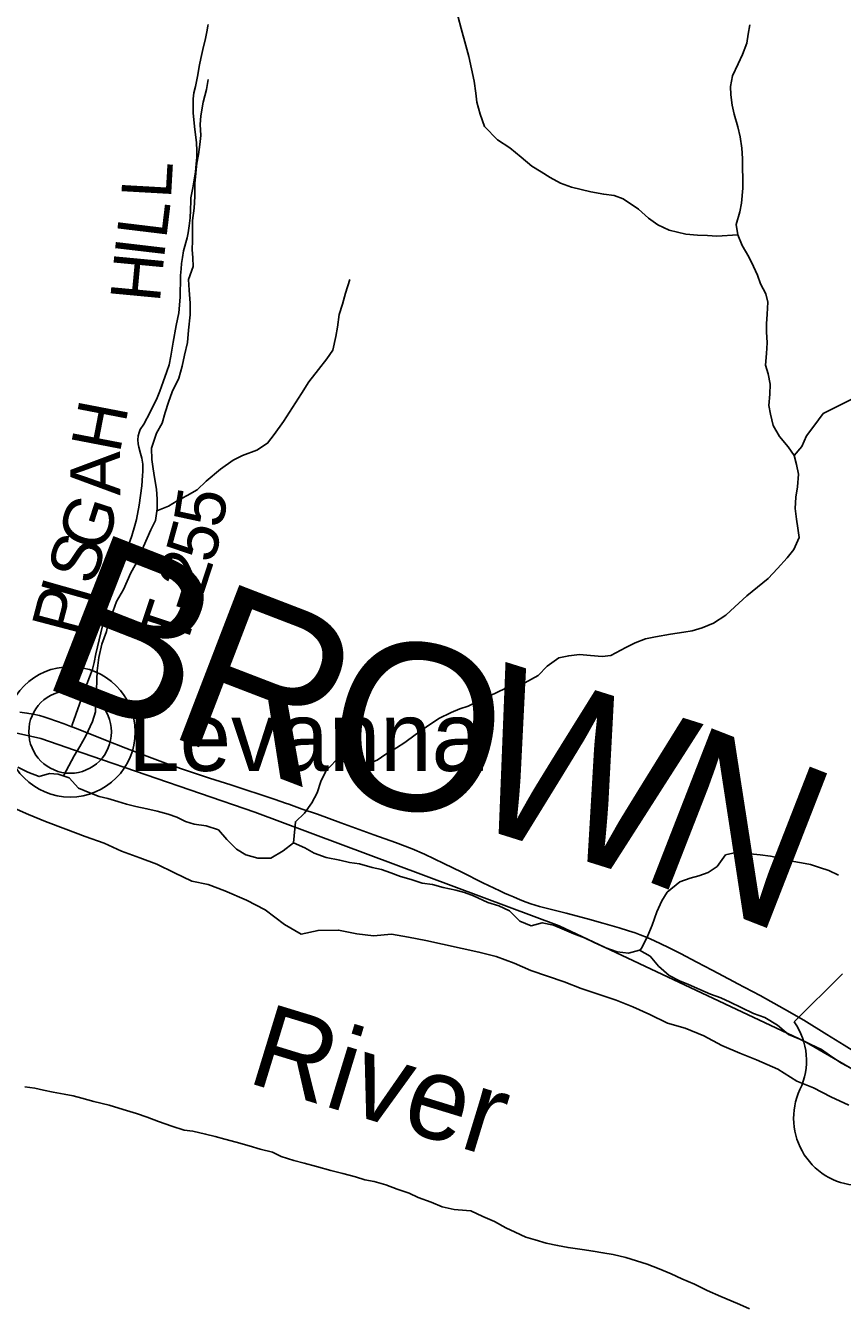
# Model space of a CAD drawing. Extents: x 0 to 34, y 0 to 22.
# Drawn here: x 3.024 to 3.956, y 18.308 to 19.77 of the extents above; entities that cross this region are included whole.
import ezdxf

# ---------------------------------------------------------------- set-up
doc = ezdxf.new("R2010")
doc.units = 0
for name, color, linetype in [('Default', 7, 'Continuous'), ('GM_X_County_Text', 7, 'Continuous'), ('GM_X_Major_River', 7, 'Continuous'), ('GM_X_Major_River_Text', 7, 'Continuous'), ('GM_X_Minor_River', 7, 'Continuous'), ('GM_X_Rail_Line', 7, 'Continuous'), ('GM_X_Township_Road', 7, 'Continuous'), ('GM_X_Township_Road_Text', 7, 'Continuous'), ('GM_X_Unincorporated', 7, 'Continuous'), ('GM_X_Unincorporated_Location', 7, 'Continuous'), ('GM_X_Unincorporated_Text', 7, 'Continuous'), ('GM_X_US_Route', 7, 'Continuous'), ('GM_X_US_Shield', 7, 'Continuous'), ('SH_Cut_Line', 7, 'Continuous')]:
    doc.layers.add(name, color=color, linetype=linetype)

msp = doc.modelspace()

# ---------------------------------------------------------------- linework, layer by layer
at = {"layer": 'Default'}
msp.add_lwpolyline([(3.0072, 18.8782), (3.0269, 18.8695), (3.0466, 18.8615), (3.0697, 18.8528), (3.0917, 18.8444), (3.1133, 18.8368), (3.1334, 18.8277), (3.1542, 18.8201), (3.1736, 18.8129), (3.1936, 18.8031), (3.2134, 18.7936), (3.2323, 18.7898), (3.2512, 18.7826), (3.2759, 18.7719), (3.2975, 18.7609), (3.3195, 18.7439), (3.3384, 18.7332), (3.3577, 18.7374), (3.3812, 18.7378), (3.4021, 18.7336), (3.421, 18.731), (3.4415, 18.7332), (3.4608, 18.7298), (3.4809, 18.7257), (3.5413, 18.7127), (3.561, 18.7074), (3.5815, 18.6998), (3.6006, 18.6915), (3.6386, 18.6786), (3.658, 18.671), (3.6777, 18.6645), (3.6982, 18.6577), (3.7171, 18.6501), (3.7365, 18.6413), (3.7569, 18.6315), (3.777, 18.6258), (3.7983, 18.617), (3.8187, 18.606), (3.8392, 18.5973), (3.8582, 18.5897), (3.8828, 18.5791), (3.9044, 18.5654), (3.9234, 18.5578), (3.9431, 18.5476), (3.9639, 18.5381)], dxfattribs=at)
at = {"layer": 'GM_X_Major_River'}
for points in [[(3.5353, 18.7768), (3.5251, 18.7807), (3.515, 18.7832), (3.5007, 18.7864), (3.4882, 18.7896), (3.4765, 18.7913), (3.4641, 18.7953), (3.4517, 18.7989), (3.4408, 18.8029), (3.4303, 18.8068), (3.4194, 18.8093), (3.4051, 18.8133), (3.3937, 18.815), (3.3824, 18.8174), (3.367, 18.8207), (3.3531, 18.8254), (3.3426, 18.8317), (3.3295, 18.8372), (3.318, 18.8282), (3.3039, 18.8197), (3.2891, 18.8199), (3.2752, 18.8236), (3.2647, 18.8302), (3.2535, 18.841), (3.2439, 18.8521), (3.23, 18.8565), (3.2164, 18.8586), (3.2062, 18.8618), (3.1965, 18.8665), (3.1867, 18.87), (3.1739, 18.8733), (3.1622, 18.8761), (3.1498, 18.8786), (3.1389, 18.8814), (3.1291, 18.8846), (3.1178, 18.8878), (3.1076, 18.8902), (3.0971, 18.8945), (3.0843, 18.8996), (3.0736, 18.9116), (3.0608, 18.9155), (3.051, 18.9165), (3.0392, 18.9128), (3.0264, 18.918), (3.0148, 18.9238)], [(3.9678, 18.5792), (3.9554, 18.5858), (3.9456, 18.5924), (3.9325, 18.6013), (3.9204, 18.6072), (3.908, 18.6134), (3.8948, 18.6185), (3.8824, 18.6293), (3.8678, 18.6379), (3.8549, 18.6426), (3.841, 18.6492), (3.8282, 18.6555), (3.8177, 18.6605), (3.806, 18.6645), (3.7935, 18.67), (3.7807, 18.6755), (3.7705, 18.6798), (3.7585, 18.686), (3.7465, 18.6964), (3.7368, 18.7079), (3.7247, 18.7149), (3.7122, 18.7113), (3.6993, 18.713), (3.6865, 18.7173), (3.6729, 18.7236), (3.662, 18.7287), (3.6499, 18.7334), (3.6364, 18.7393), (3.6266, 18.7432), (3.6137, 18.746), (3.6012, 18.7424), (3.5883, 18.7479), (3.5764, 18.7598), (3.5643, 18.7653), (3.5515, 18.7693), (3.5353, 18.7768)], [(3.0229, 18.5589), (3.0342, 18.5572), (3.044, 18.5552), (3.0553, 18.5527), (3.0677, 18.5506), (3.0779, 18.5486), (3.0881, 18.5458), (3.1016, 18.5422), (3.1193, 18.5381)], [(3.1193, 18.5381), (3.1351, 18.5329), (3.1505, 18.5285), (3.1626, 18.5242), (3.1754, 18.5194), (3.1908, 18.5139), (3.2047, 18.5095), (3.2149, 18.5082), (3.2292, 18.505), (3.2401, 18.5022), (3.2514, 18.4993), (3.2642, 18.4957), (3.2789, 18.4917), (3.2917, 18.4877), (3.3056, 18.4841), (3.3157, 18.4794), (3.33, 18.4746), (3.3417, 18.4718), (3.356, 18.4678), (3.3722, 18.4634), (3.3861, 18.4601), (3.4004, 18.4561), (3.411, 18.4529), (3.4219, 18.4509), (3.4351, 18.4469), (3.4482, 18.4421), (3.4617, 18.4374), (3.4719, 18.4327), (3.4869, 18.4271), (3.4993, 18.422), (3.5132, 18.4188), (3.5272, 18.4178), (3.5322, 18.4175)], [(3.5322, 18.4175), (3.546, 18.4109), (3.5591, 18.405), (3.5723, 18.398), (3.5829, 18.3929), (3.5949, 18.3874), (3.6055, 18.3843), (3.6183, 18.3803), (3.6312, 18.3778), (3.6433, 18.3754), (3.6592, 18.3733), (3.6717, 18.3712), (3.683, 18.3695), (3.6947, 18.3675), (3.7091, 18.3639), (3.7212, 18.3603), (3.7336, 18.3563), (3.7472, 18.3512), (3.7608, 18.3453), (3.7732, 18.3399), (3.7875, 18.3336), (3.8022, 18.3266), (3.8177, 18.3195), (3.8294, 18.3148), (3.8392, 18.3105), (3.8505, 18.3054)]]:
    msp.add_lwpolyline(points, dxfattribs=at)
at = {"layer": 'GM_X_Minor_River'}
for points in [[(3.5164, 19.7895), (3.5178, 19.7796), (3.5213, 19.7666), (3.5263, 19.7472), (3.5299, 19.7346), (3.5331, 19.7205), (3.5359, 19.7065), (3.5379, 19.6928), (3.5392, 19.6825), (3.5428, 19.6688), (3.5479, 19.6547), (3.5627, 19.6394)], [(3.5409, 18.9989), (3.562, 19.009), (3.5723, 19.0138), (3.5833, 19.0167), (3.594, 19.02), (3.6089, 19.0281), (3.6192, 19.039), (3.6326, 19.0483), (3.644, 19.0508), (3.6562, 19.0522), (3.669, 19.0509), (3.6823, 19.0499), (3.6922, 19.0509), (3.7093, 19.0602), (3.72, 19.0657), (3.7315, 19.0701), (3.7432, 19.0723), (3.76, 19.0754), (3.7752, 19.0775), (3.785, 19.0793), (3.7965, 19.0825), (3.8094, 19.0881), (3.8232, 19.097), (3.8335, 19.1067), (3.8473, 19.119), (3.8596, 19.1291), (3.8715, 19.1388), (3.8822, 19.1504), (3.8934, 19.1624), (3.9011, 19.1722), (3.9069, 19.1858), (3.9056, 19.1964), (3.9042, 19.2067), (3.9024, 19.2188), (3.9033, 19.2317), (3.905, 19.2434), (3.9063, 19.2578), (3.9042, 19.2692), (3.9013, 19.2791), (3.8946, 19.2891), (3.8845, 19.301), (3.8775, 19.3136), (3.8742, 19.3265), (3.8724, 19.3364), (3.8737, 19.3493), (3.8739, 19.3607), (3.8718, 19.3724), (3.8685, 19.3824), (3.8698, 19.3956), (3.8707, 19.4077), (3.8697, 19.4203), (3.8698, 19.4297), (3.8707, 19.4404), (3.8713, 19.4544), (3.8691, 19.4639), (3.8628, 19.4753), (3.8595, 19.4849), (3.8551, 19.4948), (3.8496, 19.5059), (3.8421, 19.5189), (3.837, 19.5311), (3.8352, 19.5428), (3.8392, 19.5572), (3.8412, 19.5674), (3.8426, 19.5845), (3.8427, 19.5955), (3.8425, 19.6072), (3.8422, 19.6182), (3.8416, 19.63), (3.8399, 19.6429), (3.837, 19.6543), (3.833, 19.6688), (3.8305, 19.6791), (3.8291, 19.6908), (3.8285, 19.7003), (3.8309, 19.7124), (3.8375, 19.7264), (3.8422, 19.7369), (3.8473, 19.7498), (3.849, 19.76), (3.8506, 19.7706)], [(3.0671, 18.9136), (3.0792, 18.9367), (3.0858, 18.9472), (3.0924, 18.9592), (3.1003, 18.9758), (3.1035, 18.9867), (3.1041, 19.0015), (3.1046, 19.011), (3.1052, 19.0231), (3.1054, 19.0334), (3.1075, 19.0489), (3.1108, 19.064), (3.116, 19.0783), (3.1188, 19.0912), (3.1239, 19.1021), (3.1275, 19.1127), (3.1357, 19.1262), (3.144, 19.1454), (3.1521, 19.1601), (3.1585, 19.1755), (3.1667, 19.1944), (3.1722, 19.2053), (3.1739, 19.2186), (3.1741, 19.2295), (3.1732, 19.2409), (3.1711, 19.2543), (3.1694, 19.2641), (3.168, 19.2748), (3.1675, 19.2877), (3.1731, 19.3047), (3.1797, 19.316), (3.1833, 19.3284), (3.1869, 19.3401), (3.1913, 19.3518), (3.1987, 19.3676), (3.2027, 19.3812), (3.2052, 19.3937), (3.2085, 19.4081), (3.2098, 19.4225), (3.2116, 19.4399), (3.2115, 19.4532), (3.2106, 19.468), (3.2096, 19.4801), (3.2152, 19.4948), (3.2146, 19.5047), (3.214, 19.5142), (3.2145, 19.5244), (3.2144, 19.5369), (3.2145, 19.5476), (3.2163, 19.5616), (3.2169, 19.5748), (3.2171, 19.5896), (3.2181, 19.6014), (3.2194, 19.6127), (3.2211, 19.6229), (3.2228, 19.6343), (3.2237, 19.6445), (3.2232, 19.6571), (3.2237, 19.6669), (3.2266, 19.6824), (3.2302, 19.6968), (3.2323, 19.7085)], [(3.837, 19.5311), (3.8131, 19.5295), (3.8025, 19.5304), (3.7911, 19.5309), (3.7775, 19.5319), (3.7586, 19.5363), (3.7457, 19.5425), (3.7352, 19.5502), (3.7236, 19.5602), (3.7063, 19.5722), (3.6957, 19.5758), (3.684, 19.5775), (3.6693, 19.5803), (3.6583, 19.5827), (3.647, 19.5855), (3.6345, 19.5902), (3.6228, 19.5965), (3.6123, 19.6031), (3.6018, 19.6093), (3.5898, 19.6197), (3.5766, 19.6305), (3.5627, 19.6394)], [(3.1736, 19.216), (3.1868, 19.2214), (3.1968, 19.2277), (3.2082, 19.2336), (3.2197, 19.2402), (3.2301, 19.2499), (3.2462, 19.2637), (3.2608, 19.2741), (3.2714, 19.2793), (3.2878, 19.2854), (3.3001, 19.2932), (3.3074, 19.3034), (3.3183, 19.318), (3.3287, 19.3341), (3.3388, 19.3499), (3.347, 19.3634), (3.3582, 19.3773), (3.3679, 19.3897), (3.3745, 19.3994), (3.3781, 19.4149), (3.3798, 19.4259), (3.382, 19.4403), (3.3856, 19.452), (3.3892, 19.4644), (3.394, 19.4803)], [(3.9013, 19.2791), (3.9101, 19.2896), (3.9156, 19.3017), (3.9237, 19.3126), (3.9345, 19.3272), (3.949, 19.3346), (3.9696, 19.3446)], [(3.3295, 18.8372), (3.3319, 18.8614), (3.3423, 18.8711), (3.3505, 18.8828), (3.3567, 18.8944), (3.3607, 18.9073), (3.3666, 18.9189), (3.3781, 18.9313), (3.3917, 18.9295), (3.4019, 18.9267), (3.4152, 18.9277), (3.4251, 18.9317), (3.435, 18.9384), (3.4472, 18.9458), (3.4568, 18.9517), (3.4687, 18.9606), (3.4817, 18.9695), (3.4955, 18.9791), (3.5096, 18.9861), (3.5195, 18.9902), (3.529, 18.9934), (3.5409, 18.9989)], [(3.7253, 18.7146), (3.727, 18.7171), (3.7336, 18.7295), (3.7391, 18.7435), (3.7446, 18.7586), (3.7501, 18.771), (3.7563, 18.7808), (3.7708, 18.7928), (3.7826, 18.7971), (3.7925, 18.7997), (3.8032, 18.8033), (3.8135, 18.8104), (3.8231, 18.8235), (3.8346, 18.8264), (3.8474, 18.8251), (3.8626, 18.8234), (3.8743, 18.8221), (3.8868, 18.8193), (3.8989, 18.8165), (3.9098, 18.8144), (3.9201, 18.8124), (3.9303, 18.8092), (3.9408, 18.8057), (3.9521, 18.8002)]]:
    msp.add_lwpolyline(points, dxfattribs=at)
at = {"layer": 'GM_X_Rail_Line'}
msp.add_lwpolyline([(4.6895, 18.1137), (4.6296, 18.1567), (4.5798, 18.1927), (4.4784, 18.2777), (4.364, 18.3544), (4.2732, 18.4099), (4.1565, 18.4748), (4.0563, 18.5278), (3.9136, 18.6104), (3.633, 18.7426), (3.5445, 18.7756), (3.2856, 18.8723), (3.0993, 18.936), (3.041, 18.9562), (2.9951, 18.9667), (2.9337, 18.9715), (2.8642, 18.9726), (2.7699, 18.9856), (2.7152, 18.9964), (2.6303, 19.0094), (2.3595, 19.0564), (2.3142, 19.0671)], dxfattribs=at)
at = {"layer": 'GM_X_Township_Road'}
msp.add_lwpolyline([(3.0765, 18.9698), (3.0771, 18.9719), (3.0893, 19.0072), (3.0968, 19.0263), (3.1, 19.0355), (3.1022, 19.0431), (3.104, 19.0529), (3.1096, 19.0769), (3.1126, 19.0898), (3.1155, 19.1049), (3.1195, 19.1179), (3.1223, 19.1267), (3.1267, 19.1382), (3.134, 19.1566), (3.1402, 19.1735), (3.145, 19.1875), (3.1486, 19.1993), (3.1502, 19.2063), (3.1533, 19.2225), (3.1564, 19.2445), (3.1573, 19.2565), (3.1578, 19.2612), (3.1578, 19.2651), (3.1576, 19.2694), (3.1563, 19.2761), (3.1551, 19.2816), (3.1529, 19.2889), (3.1524, 19.2926), (3.1519, 19.2973), (3.1522, 19.3016), (3.1534, 19.3056), (3.1547, 19.3091), (3.1586, 19.3152), (3.166, 19.3289), (3.1695, 19.3359), (3.1732, 19.3432), (3.177, 19.3527), (3.1809, 19.3633), (3.1852, 19.3753), (3.1875, 19.3829), (3.1896, 19.3926), (3.1923, 19.4088), (3.1957, 19.4278), (3.1987, 19.4422), (3.2001, 19.4601), (3.2004, 19.4676), (3.2007, 19.4758), (3.2005, 19.4848), (3.2013, 19.4924), (3.2019, 19.4983), (3.2029, 19.5051), (3.2041, 19.5128), (3.2082, 19.5278), (3.2092, 19.5332), (3.2104, 19.5412), (3.2115, 19.5504), (3.2119, 19.5593), (3.2123, 19.57), (3.2124, 19.5733), (3.213, 19.5771), (3.2147, 19.5846), (3.2158, 19.5917), (3.2176, 19.6027), (3.2187, 19.612), (3.2191, 19.6194), (3.2192, 19.6275), (3.2188, 19.6361), (3.2165, 19.6549), (3.2151, 19.6702), (3.2151, 19.6782), (3.215, 19.6864), (3.2158, 19.693), (3.2179, 19.7003), (3.2199, 19.7119), (3.2223, 19.7252), (3.2238, 19.7324), (3.2261, 19.7425), (3.229, 19.7551), (3.2311, 19.7647), (3.232, 19.7695), (3.2323, 19.7713)], dxfattribs=at)
at = {"layer": 'GM_X_Unincorporated'}
for radius in [0.0744, 0.0472]:
    msp.add_circle((3.0746, 18.9639), radius, dxfattribs=at)
at = {"layer": 'GM_X_Unincorporated_Location'}
msp.add_line((3.0746, 18.9639), (3.0746, 18.9639), dxfattribs=at)
at = {"layer": 'GM_X_US_Route'}
for points in [[(3.0172, 18.9863), (3.0252, 18.9854), (3.0324, 18.9842), (3.0396, 18.9825), (3.0446, 18.981), (3.0503, 18.9793), (3.0678, 18.9732), (3.0755, 18.9702)], [(3.0755, 18.9702), (3.0765, 18.9698), (3.0818, 18.9677), (3.115, 18.9546), (3.1383, 18.9453), (3.1532, 18.9395), (3.1864, 18.9269), (3.203, 18.9214), (3.2176, 18.9165), (3.2336, 18.9112), (3.2581, 18.9034), (3.3088, 18.8867), (3.3204, 18.8827)], [(3.3204, 18.8827), (3.3242, 18.8814), (3.3395, 18.8758), (3.357, 18.8699), (3.3838, 18.86), (3.4214, 18.8464), (3.4462, 18.8375), (3.4652, 18.8303), (3.4791, 18.8244), (3.5012, 18.8138), (3.5218, 18.8038), (3.5459, 18.7915), (3.5589, 18.7855), (3.5654, 18.7824), (3.5706, 18.7799), (3.5752, 18.7778), (3.5807, 18.7755), (3.5884, 18.7724), (3.5954, 18.7695), (3.6008, 18.7678), (3.6104, 18.7648), (3.6411, 18.7572), (3.6652, 18.7506), (3.683, 18.7455), (3.7014, 18.7401), (3.7122, 18.7368), (3.7198, 18.7344), (3.7257, 18.7324), (3.7337, 18.7292), (3.742, 18.7254), (3.757, 18.7183), (3.7717, 18.7109), (3.7903, 18.701), (3.8077, 18.692), (3.8329, 18.6788), (3.8364, 18.6769)], [(3.8364, 18.6769), (3.8626, 18.6629), (3.8903, 18.6476), (3.9123, 18.635), (3.9387, 18.6187), (3.9583, 18.6063), (3.9778, 18.5942), (3.9898, 18.5864), (4.0063, 18.5762), (4.0294, 18.562), (4.0602, 18.5443), (4.0923, 18.5265), (4.1484, 18.4985), (4.1763, 18.4847), (4.2162, 18.4656)]]:
    msp.add_lwpolyline(points, dxfattribs=at)
at = {"layer": 'GM_X_US_Shield'}
msp.add_line((3.9565, 18.6878), (3.9015, 18.6329), dxfattribs=at)
for centre, start, end in [((3.8385, 18.5888), 334.5471, 35.0009), ((3.9776, 18.523), 154.8319, 270.6383)]:
    msp.add_arc(centre, 0.0769, start, end, dxfattribs=at)
at = {"layer": 'SH_Cut_Line'}
msp.add_lwpolyline([(3.0072, 18.8782), (3.0269, 18.8695), (3.0466, 18.8615), (3.0697, 18.8528), (3.0917, 18.8444), (3.1133, 18.8368), (3.1334, 18.8277), (3.1542, 18.8201), (3.1736, 18.8129), (3.1936, 18.8031), (3.2134, 18.7936), (3.2323, 18.7898), (3.2512, 18.7826), (3.2759, 18.7719), (3.2975, 18.7609), (3.3195, 18.7439), (3.3384, 18.7332), (3.3577, 18.7374), (3.3812, 18.7378), (3.4021, 18.7336), (3.421, 18.731), (3.4415, 18.7332), (3.4608, 18.7298), (3.4809, 18.7257), (3.5413, 18.7127), (3.561, 18.7074), (3.5815, 18.6998), (3.6006, 18.6915), (3.6386, 18.6786), (3.658, 18.671), (3.6777, 18.6645), (3.6982, 18.6577), (3.7171, 18.6501), (3.7365, 18.6413), (3.7569, 18.6315), (3.777, 18.6258), (3.7983, 18.617), (3.8187, 18.606), (3.8392, 18.5973), (3.8582, 18.5897), (3.8828, 18.5791), (3.9044, 18.5654), (3.9234, 18.5578), (3.9431, 18.5476), (3.9639, 18.5381)], dxfattribs=at)

# ---------------------------------------------------------------- texts
at = {"layer": 'GM_X_County_Text'}
for s, rotation, p in [('B', 338.6898, (3.0358, 19.0185)), ('R', 338.9701, (3.1804, 18.9622)), ('O', 347.7633, (3.3547, 18.8978)), ('W', 342.5472, (3.5139, 18.8634)), ('N', 338.6843, (3.719, 18.7991))]:
    msp.add_text(s, height=0.1894, rotation=rotation, dxfattribs=at).set_placement(p)
at = {"layer": 'GM_X_Major_River_Text'}
msp.add_text('River', height=0.0947, rotation=343.0022, dxfattribs=at).set_placement((3.2747, 18.5645))
at = {"layer": 'GM_X_Township_Road_Text'}
for s, rotation, p in [('L', 86.7733, (3.1897, 19.5715)), ('L', 83.0855, (3.1843, 19.5254)), ('I', 83.3223, (3.1816, 19.5023)), ('H', 84.6281, (3.1769, 19.4528)), ('H', 79.0803, (3.1312, 19.2807)), ('A', 90.2693, (3.1318, 19.2336)), ('5', 81.0918, (3.2485, 19.1952)), ('G', 72.115, (3.1134, 19.1667)), ('5', 74.5909, (3.2377, 19.1546)), ('S', 71.1601, (3.1007, 19.1294)), ('2', 71.9498, (3.2261, 19.1186)), ('I', 74.1597, (3.0946, 19.1077)), ('P', 75.2729, (3.0849, 19.0709)), ('-', 71.7545, (3.2187, 19.0963)), ('T', 71.7128, (3.2053, 19.0559))]:
    msp.add_text(s, height=0.0568, rotation=rotation, dxfattribs=at).set_placement(p)
at = {"layer": 'GM_X_Unincorporated_Text'}
msp.add_text('Levanna', height=0.07898, rotation=0, dxfattribs=at).set_placement((3.1409, 18.9193))

doc.saveas('drawing.dxf')
